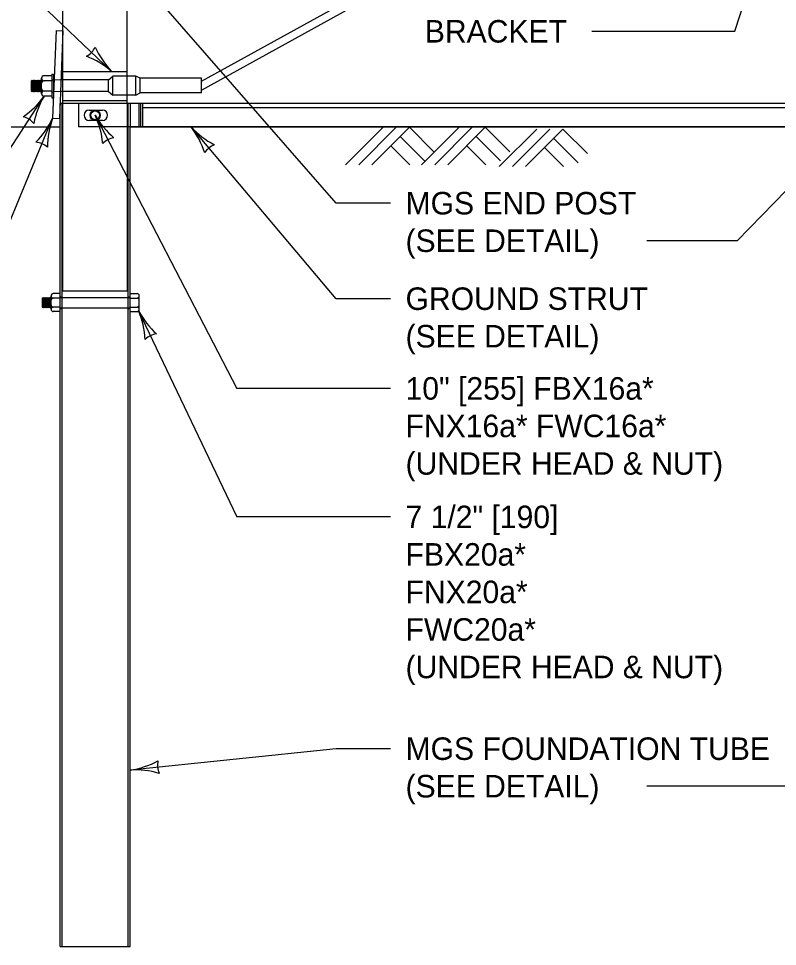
# Model space of a CAD drawing. Extents: x 49991.4 to 50021, y 49987.6 to 50011.4.
# Drawn here: x 50001.141 to 50003.165, y 49992.871 to 49995.344 of the extents above; entities that cross this region are included whole.
import ezdxf

# ---------------------------------------------------------------- set-up
doc = ezdxf.new("R2010")
doc.units = 0
for name, color, linetype in [('Level 1', 7, 'Continuous'), ('Level 2', 7, 'Continuous'), ('Level 3', 7, 'Continuous'), ('Level 4', 7, 'Continuous')]:
    doc.layers.add(name, color=color, linetype=linetype)

msp = doc.modelspace()

# ---------------------------------------------------------------- linework, layer by layer
at = {"layer": 'Level 1'}
for p, q in [((50001.2594, 49995.1173), (50001.2594, 49995.6473)), ((50001.431, 49995.1175), (50001.431, 49995.6473)), ((50001.6293, 49995.177), (50002.4808, 49995.6473)), ((50001.6293, 49995.1536), (50002.5232, 49995.6473)), ((50001.2411, 49995.3124), (50001.2318, 49995.0782)), ((50001.2411, 49995.3124), (50001.2594, 49995.3117)), ((50001.2594, 49995.3117), (50001.2501, 49995.0775)), ((50001.2023, 49995.1439), (50001.2023, 49995.1851)), ((50001.2297, 49995.1918), (50001.209, 49995.1918)), ((50001.2297, 49995.1957), (50001.2297, 49995.1332)), ((50001.2297, 49995.1957), (50001.234, 49995.1957)), ((50001.2297, 49995.1811), (50001.234, 49995.1811)), ((50001.234, 49995.1957), (50001.234, 49995.1332)), ((50001.2359, 49995.1809), (50001.234, 49995.1809)), ((50001.3812, 49995.1809), (50001.2542, 49995.1809)), ((50001.3812, 49995.1809), (50001.3927, 49995.1907)), ((50001.3812, 49995.1497), (50001.3812, 49995.1809)), ((50001.4535, 49995.1907), (50001.3927, 49995.1907)), ((50001.3927, 49995.1399), (50001.3927, 49995.1907)), ((50001.4535, 49995.1399), (50001.4535, 49995.1907)), ((50001.4652, 49995.1848), (50001.4535, 49995.1907)), ((50001.4652, 49995.1458), (50001.4652, 49995.1848)), ((50001.6293, 49995.1848), (50001.4652, 49995.1848)), ((50001.6293, 49995.1458), (50001.6293, 49995.1848)), ((50001.1758, 49995.1782), (50001.1773, 49995.1801)), ((50001.1758, 49995.1782), (50001.1773, 49995.1488)), ((50001.1758, 49995.1508), (50001.1758, 49995.1782)), ((50001.1773, 49995.1801), (50001.1789, 49995.1508)), ((50001.1789, 49995.1782), (50001.1773, 49995.1801)), ((50001.1789, 49995.1782), (50001.1804, 49995.1801)), ((50001.1789, 49995.1782), (50001.1804, 49995.1488)), ((50001.182, 49995.1782), (50001.1804, 49995.1801)), ((50001.1804, 49995.1801), (50001.182, 49995.1508)), ((50001.182, 49995.1782), (50001.1835, 49995.1801)), ((50001.182, 49995.1782), (50001.1835, 49995.1488)), ((50001.185, 49995.1782), (50001.1835, 49995.1801)), ((50001.1835, 49995.1801), (50001.185, 49995.1508)), ((50001.185, 49995.1782), (50001.1865, 49995.1801)), ((50001.185, 49995.1782), (50001.1865, 49995.1488)), ((50001.1881, 49995.1782), (50001.1865, 49995.1801)), ((50001.1865, 49995.1801), (50001.1881, 49995.1508)), ((50001.1881, 49995.1782), (50001.1896, 49995.1801)), ((50001.1881, 49995.1782), (50001.1896, 49995.1488)), ((50001.1912, 49995.1782), (50001.1896, 49995.1801)), ((50001.1896, 49995.1801), (50001.1912, 49995.1508)), ((50001.1912, 49995.1782), (50001.1927, 49995.1801)), ((50001.1912, 49995.1782), (50001.1927, 49995.1488)), ((50001.1943, 49995.1782), (50001.1927, 49995.1801)), ((50001.1927, 49995.1801), (50001.1943, 49995.1508)), ((50001.1943, 49995.1782), (50001.1958, 49995.1801)), ((50001.1943, 49995.1782), (50001.1958, 49995.1488)), ((50001.1973, 49995.1782), (50001.1958, 49995.1801)), ((50001.1958, 49995.1801), (50001.1973, 49995.1508)), ((50001.1973, 49995.1782), (50001.1988, 49995.1801)), ((50001.1973, 49995.1782), (50001.1988, 49995.1488)), ((50001.2004, 49995.1782), (50001.1988, 49995.1801)), ((50001.1988, 49995.1801), (50001.2004, 49995.1508)), ((50001.2004, 49995.1782), (50001.2019, 49995.1801)), ((50001.2004, 49995.1782), (50001.2019, 49995.1488)), ((50001.2019, 49995.1801), (50001.2023, 49995.1751)), ((50001.2023, 49995.1796), (50001.2019, 49995.1801)), ((50001.2297, 49995.1781), (50001.209, 49995.1781)), ((50001.1773, 49995.1488), (50001.1758, 49995.1508)), ((50001.1773, 49995.1488), (50001.1789, 49995.1508)), ((50001.1804, 49995.1488), (50001.1789, 49995.1508)), ((50001.1804, 49995.1488), (50001.182, 49995.1508)), ((50001.1835, 49995.1488), (50001.182, 49995.1508)), ((50001.1835, 49995.1488), (50001.185, 49995.1508)), ((50001.1865, 49995.1488), (50001.185, 49995.1508)), ((50001.1865, 49995.1488), (50001.1881, 49995.1508)), ((50001.1896, 49995.1488), (50001.1881, 49995.1508)), ((50001.1896, 49995.1488), (50001.1912, 49995.1508)), ((50001.1927, 49995.1488), (50001.1912, 49995.1508)), ((50001.1927, 49995.1488), (50001.1943, 49995.1508)), ((50001.1958, 49995.1488), (50001.1943, 49995.1508)), ((50001.1958, 49995.1488), (50001.1973, 49995.1508)), ((50001.1988, 49995.1488), (50001.1973, 49995.1508)), ((50001.1988, 49995.1488), (50001.2004, 49995.1508)), ((50001.2019, 49995.1488), (50001.2004, 49995.1508)), ((50001.2019, 49995.1488), (50001.2023, 49995.1494)), ((50001.2297, 49995.1508), (50001.209, 49995.1508)), ((50001.2297, 49995.1371), (50001.209, 49995.1371)), ((50001.2297, 49995.1479), (50001.234, 49995.1479)), ((50001.2297, 49995.1332), (50001.234, 49995.1332)), ((50001.2347, 49995.1497), (50001.234, 49995.1497)), ((50001.3812, 49995.1497), (50001.253, 49995.1497)), ((50001.3812, 49995.1497), (50001.3927, 49995.1399)), ((50001.4535, 49995.1399), (50001.3927, 49995.1399)), ((50001.4535, 49995.1399), (50001.4652, 49995.1458)), ((50001.6293, 49995.1458), (50001.4652, 49995.1458)), ((50001.2517, 49992.8711), (50001.2517, 49995.1175)), ((50001.4389, 49995.1175), (50001.2517, 49995.1175)), ((50003.7339, 49995.1175), (50001.3004, 49995.1175)), ((50001.3004, 49995.1175), (50001.3004, 49995.0551)), ((50001.4622, 49995.0551), (50001.4622, 49995.1175)), ((50001.4719, 49995.1175), (50001.4719, 49995.0551)), ((50001.3296, 49995.1), (50001.3647, 49995.1)), ((50001.2318, 49995.0782), (50001.2501, 49995.0775)), ((50001.3647, 49995.0727), (50001.3296, 49995.0727)), ((50000.3936, 49995.0551), (50001.2515, 49995.0551)), ((50003.7339, 49995.0551), (50001.3004, 49995.0551)), ((50001.4389, 49992.8711), (50001.4389, 49995.0551)), ((50001.4391, 49995.0551), (50003.5952, 49995.0551)), ((50002.0133, 49994.9542), (50002.1133, 49995.0542)), ((50002.0483, 49994.9542), (50002.1483, 49995.0542)), ((50002.0833, 49994.9542), (50002.1833, 49995.0542)), ((50002.1833, 49995.0542), (50002.2483, 49994.9892)), ((50002.2158, 49994.9542), (50002.3158, 49995.0542)), ((50002.2508, 49994.9542), (50002.3508, 49995.0542)), ((50002.2858, 49994.9542), (50002.3858, 49995.0542)), ((50002.3858, 49995.0542), (50002.4508, 49994.9892)), ((50002.423, 49994.9495), (50002.523, 49995.0495)), ((50002.458, 49994.9495), (50002.558, 49995.0495)), ((50002.493, 49994.9495), (50002.593, 49995.0495)), ((50002.593, 49995.0495), (50002.658, 49994.9845)), ((50002.1586, 49995.0295), (50002.2236, 49994.9645)), ((50002.3611, 49995.0295), (50002.4261, 49994.9645)), ((50002.5683, 49995.0248), (50002.6333, 49994.9598)), ((50002.1338, 49995.0047), (50002.1843, 49994.9542)), ((50002.3363, 49995.0047), (50002.3868, 49994.9542)), ((50002.5435, 49995), (50002.594, 49994.9495)), ((50001.2047, 49994.5991), (50001.206, 49994.6008)), ((50001.2047, 49994.5991), (50001.206, 49994.5735)), ((50001.2047, 49994.5752), (50001.2047, 49994.5991)), ((50001.206, 49994.6008), (50001.2074, 49994.5752)), ((50001.2074, 49994.5991), (50001.206, 49994.6008)), ((50001.2074, 49994.5991), (50001.2087, 49994.6008)), ((50001.2074, 49994.5991), (50001.2087, 49994.5735)), ((50001.2101, 49994.5991), (50001.2087, 49994.6008)), ((50001.2087, 49994.6008), (50001.2101, 49994.5752)), ((50001.2101, 49994.5991), (50001.2114, 49994.6008)), ((50001.2101, 49994.5991), (50001.2114, 49994.5735)), ((50001.2127, 49994.5991), (50001.2114, 49994.6008)), ((50001.2114, 49994.6008), (50001.2127, 49994.5752)), ((50001.2127, 49994.5991), (50001.214, 49994.6008)), ((50001.2127, 49994.5991), (50001.214, 49994.5735)), ((50001.2154, 49994.5991), (50001.214, 49994.6008)), ((50001.214, 49994.6008), (50001.2154, 49994.5752)), ((50001.2154, 49994.5991), (50001.2167, 49994.6008)), ((50001.2154, 49994.5991), (50001.2167, 49994.5735)), ((50001.2181, 49994.5991), (50001.2167, 49994.6008)), ((50001.2167, 49994.6008), (50001.2181, 49994.5752)), ((50001.2181, 49994.5991), (50001.2194, 49994.6008)), ((50001.2181, 49994.5991), (50001.2194, 49994.5735)), ((50001.2208, 49994.5991), (50001.2194, 49994.6008)), ((50001.2194, 49994.6008), (50001.2208, 49994.5752)), ((50001.2208, 49994.5991), (50001.2221, 49994.6008)), ((50001.2208, 49994.5991), (50001.2221, 49994.5735)), ((50001.2234, 49994.5991), (50001.2221, 49994.6008)), ((50001.2221, 49994.6008), (50001.2234, 49994.5752)), ((50001.2234, 49994.5991), (50001.2247, 49994.6008)), ((50001.2234, 49994.5991), (50001.2247, 49994.5735)), ((50001.2261, 49994.5991), (50001.2247, 49994.6008)), ((50001.2247, 49994.6008), (50001.2261, 49994.5752)), ((50001.2261, 49994.5991), (50001.2275, 49994.6008)), ((50001.2261, 49994.5991), (50001.2275, 49994.5735)), ((50001.2275, 49994.6008), (50001.2278, 49994.5964)), ((50001.2278, 49994.6004), (50001.2275, 49994.6008)), ((50001.2278, 49994.5692), (50001.2278, 49994.6051)), ((50001.2517, 49994.611), (50001.2336, 49994.611)), ((50001.2517, 49994.599), (50001.2336, 49994.599)), ((50001.4389, 49994.611), (50001.457, 49994.611)), ((50001.4389, 49994.599), (50001.457, 49994.599)), ((50001.4628, 49994.5692), (50001.4628, 49994.6051)), ((50001.206, 49994.5735), (50001.2047, 49994.5752)), ((50001.206, 49994.5735), (50001.2074, 49994.5752)), ((50001.2087, 49994.5735), (50001.2074, 49994.5752)), ((50001.2087, 49994.5735), (50001.2101, 49994.5752)), ((50001.2114, 49994.5735), (50001.2101, 49994.5752)), ((50001.2114, 49994.5735), (50001.2127, 49994.5752)), ((50001.214, 49994.5735), (50001.2127, 49994.5752)), ((50001.214, 49994.5735), (50001.2154, 49994.5752)), ((50001.2167, 49994.5735), (50001.2154, 49994.5752)), ((50001.2167, 49994.5735), (50001.2181, 49994.5752)), ((50001.2194, 49994.5735), (50001.2181, 49994.5752)), ((50001.2194, 49994.5735), (50001.2208, 49994.5752)), ((50001.2221, 49994.5735), (50001.2208, 49994.5752)), ((50001.2221, 49994.5735), (50001.2234, 49994.5752)), ((50001.2247, 49994.5735), (50001.2234, 49994.5752)), ((50001.2247, 49994.5735), (50001.2261, 49994.5752)), ((50001.2275, 49994.5735), (50001.2261, 49994.5752)), ((50001.2275, 49994.5735), (50001.2278, 49994.5739)), ((50001.2517, 49994.5752), (50001.2336, 49994.5752)), ((50001.2517, 49994.5633), (50001.2336, 49994.5633)), ((50001.4389, 49994.5752), (50001.457, 49994.5752)), ((50001.4389, 49994.5633), (50001.457, 49994.5633)), ((50001.2517, 49992.8711), (50001.4389, 49992.8711))]:
    msp.add_line(p, q, dxfattribs=at)
for centre, radius in [((50001.3452, 49995.0863), 0.0136), ((50001.3453, 49995.0863), 0.0117)]:
    msp.add_circle(centre, radius, dxfattribs=at)
for centre, radius, start, end in [((50001.209, 49995.1851), 0.00671, 90.1602, 180.1602), ((50001.2091, 49995.185), 0.00683, 178.7945, 268.7945), ((50001.209, 49995.1714), 0.0067, 90.0618, 177.1409), ((50001.209, 49995.1576), 0.00674, 182.0518, 269.5951), ((50001.2091, 49995.144), 0.00679, 90.896, 180.896), ((50001.2091, 49995.1439), 0.00674, 179.5221, 269.5221), ((50001.3296, 49995.0863), 0.0137, 90, 270), ((50001.3647, 49995.0863), 0.0137, 270, 90), ((50001.2337, 49994.6051), 0.00585, 90.1602, 180.1602), ((50001.2338, 49994.605), 0.00596, 178.7945, 268.7945), ((50001.2337, 49994.5932), 0.00585, 90.0618, 177.1409), ((50001.4569, 49994.6051), 0.00585, 359.8398, 89.8398), ((50001.4568, 49994.605), 0.00596, 271.2055, 1.2055), ((50001.4569, 49994.5932), 0.00585, 2.8591, 89.9382), ((50001.2337, 49994.5811), 0.00588, 182.0518, 269.5951), ((50001.2337, 49994.5693), 0.00593, 90.896, 180.896), ((50001.2337, 49994.5692), 0.00588, 179.5221, 269.5221), ((50001.4569, 49994.5811), 0.00588, 270.4049, 357.9482), ((50001.4569, 49994.5693), 0.00593, 359.104, 89.104), ((50001.4569, 49994.5692), 0.00588, 270.4779, 0.4779)]:
    msp.add_arc(centre, radius, start, end, dxfattribs=at)
at = {"layer": 'Level 3'}
for p, q in [((50003.0509, 49995.3101), (50003.1927, 49995.7413)), ((50001.9882, 49994.852), (50001.431, 49995.4894)), ((50001.1178, 49995.4611), (50001.389, 49995.2033)), ((50002.6698, 49995.3101), (50003.0509, 49995.3101)), ((50003.0572, 49994.752), (50003.6032, 49995.311)), ((50000.6742, 49994.3147), (50001.209, 49995.1371)), ((50001.3453, 49995.0863), (50001.7228, 49994.3584)), ((50000.8108, 49994.0651), (50001.2318, 49995.0782)), ((50001.9882, 49994.5975), (50001.6011, 49995.0551)), ((50002.1331, 49994.852), (50001.9882, 49994.852)), ((50003.0572, 49994.752), (50002.8169, 49994.752)), ((50002.1331, 49994.5975), (50001.9882, 49994.5975)), ((50001.4611, 49994.565), (50001.7228, 49994.016)), ((50002.1331, 49994.3584), (50001.7228, 49994.3584)), ((50002.1331, 49994.016), (50001.7228, 49994.016)), ((50001.9882, 49993.3982), (50001.4389, 49993.3411)), ((50002.1331, 49993.3982), (50001.9882, 49993.3982)), ((50003.4449, 49993.2982), (50002.8169, 49993.2982))]:
    msp.add_line(p, q, dxfattribs=at)
for centre, radius, start, end in [((50001.2961, 49995.2917), 0.0548, 298.5948, 334.3172), ((50001.5487, 49995.358), 0.2223, 203.912, 224.0955), ((50001.237, 49995.0267), 0.233, 49.2833, 68.5331), ((50001.0278, 49995.2659), 0.2223, 304.4249, 324.6084), ((50001.4104, 49995.0199), 0.233, 149.7962, 169.046), ((50001.1391, 49995.0296), 0.0548, 39.1077, 74.83), ((50001.1439, 49994.9922), 0.2223, 4.8708, 25.0543), ((50001.5466, 49995.2037), 0.233, 210.2421, 229.4919), ((50001.0302, 49995.1719), 0.2223, 314.8866, 335.0701), ((50001.4511, 49994.9995), 0.233, 160.2579, 179.5077), ((50001.4256, 49994.9187), 0.2223, 17.6824, 37.8659), ((50001.7714, 49995.2142), 0.233, 223.0537, 242.3036), ((50001.1826, 49994.9598), 0.0548, 49.5694, 85.2917), ((50001.4043, 49994.9725), 0.0548, 99.5536, 135.2759), ((50001.6839, 49994.9572), 0.0548, 112.3652, 148.0876), ((50001.2566, 49994.4777), 0.2223, 2.9466, 23.1301), ((50001.6662, 49994.6756), 0.233, 208.3179, 227.5677), ((50001.5163, 49994.4493), 0.0548, 97.6294, 133.3517), ((50001.4034, 49993.5714), 0.233, 278.7601, 298.0099), ((50001.5664, 49993.3544), 0.0548, 168.0716, 203.7939), ((50001.4528, 49993.1192), 0.2223, 73.3888, 93.5723)]:
    msp.add_arc(centre, radius, start, end, dxfattribs=at)
at = {"layer": 'Level 4'}
for p, q in [((50001.2359, 49995.1816), (50001.2542, 49995.1809)), ((50001.2594, 49995.2033), (50001.431, 49995.2033)), ((50001.2347, 49995.1505), (50001.253, 49995.1497)), ((50001.2576, 49992.8711), (50001.2576, 49995.1175)), ((50001.2594, 49995.1253), (50001.431, 49995.1253)), ((50001.2594, 49994.6183), (50001.2594, 49995.1175)), ((50001.431, 49995.1175), (50001.431, 49994.6183)), ((50001.433, 49992.8711), (50001.433, 49995.1175)), ((50001.4389, 49995.1175), (50001.4389, 49995.0551)), ((50001.4661, 49995.1175), (50001.4661, 49995.0551)), ((50001.4719, 49995.1068), (50003.5624, 49995.1068)), ((50001.2594, 49994.6183), (50001.431, 49994.6183)), ((50001.2517, 49994.6027), (50001.2576, 49994.6027)), ((50001.2517, 49994.6008), (50001.4389, 49994.6008)), ((50001.433, 49994.6027), (50001.4389, 49994.6027)), ((50001.2517, 49994.5735), (50001.4389, 49994.5735)), ((50001.2517, 49994.5715), (50001.2576, 49994.5715)), ((50001.433, 49994.5715), (50001.4389, 49994.5715))]:
    msp.add_line(p, q, dxfattribs=at)

# ---------------------------------------------------------------- texts
at = {"layer": 'Level 2'}
for s, p in [('BRACKET', (50002.2245, 49995.2801)), ('MGS END POST', (50002.1731, 49994.822)), ('(SEE DETAIL)', (50002.1731, 49994.722)), ('GROUND STRUT', (50002.1731, 49994.5675)), ('(SEE DETAIL)', (50002.1731, 49994.4675)), ('10" [255] FBX16a*', (50002.1731, 49994.3284)), ('FNX16a* FWC16a*', (50002.1731, 49994.2284)), ('(UNDER HEAD & NUT)', (50002.1731, 49994.1284)), ('7 1/2" [190]', (50002.1731, 49993.986)), ('FBX20a*', (50002.1731, 49993.886)), ('FNX20a*', (50002.1731, 49993.786)), ('FWC20a*', (50002.1731, 49993.686)), ('(UNDER HEAD & NUT)', (50002.1731, 49993.586)), ('MGS FOUNDATION TUBE', (50002.1731, 49993.3682)), ('(SEE DETAIL)', (50002.1731, 49993.2682))]:
    msp.add_text(s, height=0.06, dxfattribs=at).set_placement(p)

doc.saveas('drawing.dxf')
